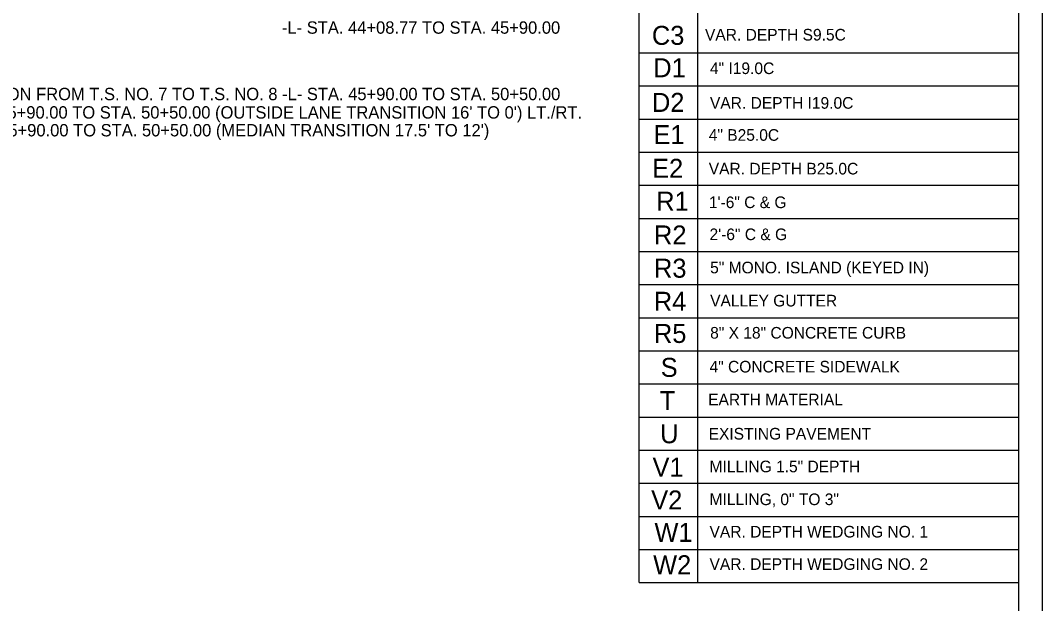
# Model space of a CAD drawing. Extents: x 957297 to 961629, y 830661 to 840840.
# Drawn here: x 959852 to 960390, y 836383 to 836690 of the extents above; entities that cross this region are included whole.
import ezdxf

# ---------------------------------------------------------------- set-up
doc = ezdxf.new("R2010")
doc.units = 0
for name, color, linetype in [('Old_Level_1', 7, 'Continuous'), ('Old_Level_50', 7, 'Continuous'), ('Prop Pavement Schedule Description CELL', 7, 'Continuous'), ('Sheet Plot Border Inside CELL', 7, 'Continuous'), ('Sheet Typical CELL', 7, 'Continuous')]:
    doc.layers.add(name, color=color, linetype=linetype)

msp = doc.modelspace()

# ---------------------------------------------------------------- linework, layer by layer
at = {"layer": 'Old_Level_50'}
for p, q in [((960177.75, 836394.2), (960177.75, 836744.41)), ((960208.48, 836725.57), (960208.48, 836394.2)), ((960177.75, 836673.24), (960377.79, 836673.24)), ((960177.75, 836655.8), (960377.79, 836655.8)), ((960177.75, 836638.36), (960377.79, 836638.36)), ((960177.75, 836620.92), (960377.79, 836620.92)), ((960177.75, 836620.92), (960377.79, 836620.92)), ((960177.75, 836603.48), (960377.79, 836603.48)), ((960177.75, 836586.04), (960377.79, 836586.04)), ((960177.75, 836568.6), (960377.79, 836568.6)), ((960177.75, 836551.16), (960377.79, 836551.16)), ((960177.75, 836533.72), (960377.79, 836533.72)), ((960177.75, 836516.28), (960377.79, 836516.28)), ((960177.75, 836498.84), (960377.79, 836498.84)), ((960177.75, 836481.4), (960377.79, 836481.4)), ((960177.75, 836463.96), (960377.79, 836463.96)), ((960177.75, 836446.52), (960377.79, 836446.52)), ((960177.75, 836429.08), (960377.79, 836429.08)), ((960177.75, 836411.64), (960377.79, 836411.64)), ((960177.75, 836394.2), (960377.79, 836394.2))]:
    msp.add_line(p, q, dxfattribs=at)
at = {"layer": 'Sheet Plot Border Inside CELL'}
msp.add_lwpolyline([(960390.3, 836974.7), (958723.8, 836974.7), (958723.8, 835919.6), (960390.3, 835919.6)], close=True, dxfattribs=at)
at = {"layer": 'Sheet Typical CELL'}
msp.add_lwpolyline([(960377.8, 836972.15), (958877.8, 836972.15), (958877.8, 835922.15), (960377.8, 835922.15)], close=True, dxfattribs=at)

# ---------------------------------------------------------------- texts
at = {"layer": 'Old_Level_1'}
for s, p in [('-L- STA. 44+08.77 TO STA. 45+90.00', (959989.57, 836683.31)), ('NOTE: TRANSITION FROM T.S. NO. 7 TO T.S. NO. 8 -L- STA. 45+90.00 TO STA. 50+50.00', (959775.89, 836648.31)), ("-L- STA. 45+90.00 TO STA. 50+50.00 (OUTSIDE LANE TRANSITION 16' TO 0') LT./RT.", (959805.29, 836638.62)), ("-L- STA. 45+90.00 TO STA. 50+50.00 (MEDIAN TRANSITION 17.5' TO 12')", (959805.75, 836629.24))]:
    msp.add_text(s, height=6.5088, dxfattribs=at).set_placement(p)
at = {"layer": 'Prop Pavement Schedule Description CELL'}
for s, height, p in [('C3', 10.005, (960184.48, 836677.44)), ('VAR. DEPTH S9.5C', 6.1255, (960212.45, 836679.73)), ('D1', 10.005, (960185.21, 836660.38)), ('4" I19.0C', 6.126, (960215.07, 836662.06)), ('D2', 10.005, (960184.51, 836642.14)), ('VAR. DEPTH I19.0C', 6.1255, (960215.07, 836643.81)), ('E1', 10.005, (960185.29, 836625.16)), ('4" B25.0C', 6.126, (960214.44, 836626.92)), ('E2', 10.005, (960184.59, 836607.43)), ('VAR. DEPTH B25.0C', 6.1255, (960214.44, 836609.19)), ('R1', 10.005, (960186.77, 836590.13)), ('1\'-6" C & G', 6.1255, (960214.52, 836591.46)), ('R2', 10.005, (960185.6, 836572.32)), ('2\'-6" C & G', 6.1255, (960214.84, 836574.6)), ('R3', 10.005, (960185.6, 836554.82)), ('5" MONO. ISLAND (KEYED IN)', 6.1255, (960215.16, 836557.11)), ('R4', 10.005, (960185.5, 836537.38)), ('VALLEY GUTTER', 6.1255, (960215.16, 836539.67)), ('R5', 10.005, (960185.55, 836520.46)), ('8" X 18" CONCRETE CURB', 6.1255, (960215.16, 836522.74)), ('S', 10, (960189.13, 836502.6)), ('4" CONCRETE SIDEWALK', 6.1255, (960214.84, 836504.89)), ('T', 10, (960188.65, 836485.06)), ('EARTH MATERIAL', 6.1255, (960214.12, 836487.6)), ('U', 10, (960188.83, 836467.62)), ('EXISTING PAVEMENT', 6.1255, (960214.36, 836469.59)), ('V1', 10.005, (960184.81, 836450.04)), ('MILLING 1.5" DEPTH', 6.1255, (960214.84, 836452.33)), ('V2', 10.005, (960184.11, 836432.75)), ('MILLING, 0" TO 3" ', 6.1255, (960214.84, 836435.04)), ('W1', 10.005, (960185.83, 836415.7)), ('VAR. DEPTH WEDGING NO. 1 ', 6.1255, (960214.84, 836417.98)), ('W2', 10.005, (960185.13, 836398.63)), ('VAR. DEPTH WEDGING NO. 2 ', 6.1255, (960214.84, 836400.91))]:
    msp.add_text(s, height=height, dxfattribs=at).set_placement(p)

doc.saveas('drawing.dxf')
